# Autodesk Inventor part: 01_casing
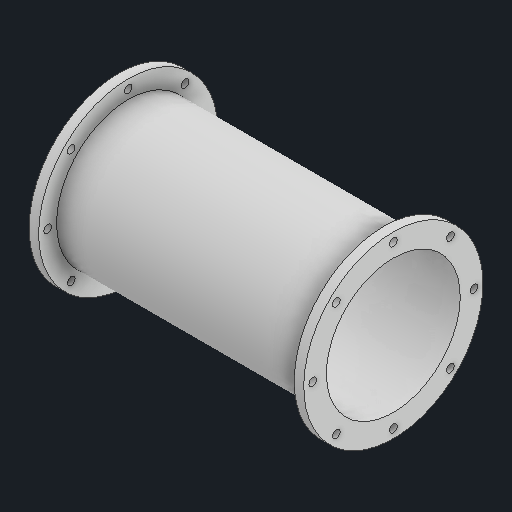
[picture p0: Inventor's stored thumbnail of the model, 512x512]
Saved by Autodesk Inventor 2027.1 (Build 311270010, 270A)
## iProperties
Created: 2026-10
Part Number: 01_casing
Material: Generic
Document SubType Name: Modeling
Designer: BHAVAN KUMAR
Density: 1 g/cm^3
Appearance: Default
Title: Turbojet Casing
Part Number: 01-CASING
Description: Outer casing tube with flanges
Author: BHAVAN KUMAR
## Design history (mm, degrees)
sketch "Sketch1"
  geometry: L1 (0, 0)-(350, 0); L2 (0, 60)-(230, 60); L3 (230, 60)-(230, 56); L4 (230, 56)-(0, 56); L5 (0, 56)-(0, 60)
  constraints: 10 end point, 2 horizontal, 2 parallel, 1 perpendicular
  dimensions: "d8" = 230 distance of L2.start L2.end (= casing_len); "d9" = 60 distance from line of L2 L1.end (= 0.5 x casing_od); "d10" = 56 distance of L1.start L4.end (= 0.5 x casing_od - casing_wall); "d11" = 0 distance from line of L1.start L5
revolve "Revolution1" sketch "Sketch1" stored, may be unused: angle "d12" = 90 deg
sketch "Sketch2"
  geometry: L1 (0, 75)-(8, 75); L2 (8, 75)-(8, 60); L3 (8, 60)-(0, 60); L4 (0, 60)-(0, 75); L5 (0, -60)-(0, 60) reference; L6 (222, 75)-(230, 75); L7 (230, 75)-(230, 60); L8 (230, 60)-(222, 60); L9 (222, 60)-(222, 75); 1 further point
  constraints: 16 end point, 4 parallel, 2 horizontal, 2 perpendicular
  dimensions: "d13" = 8 distance of L1.start L1.end (= flange_t); "d14" = 60 distance from line of point (0, 0) L3 (= 0.5 x casing_od); "d15" = 75 distance from line of point (0, 0) L1 (= 0.5 x flange_od); "d16" = 0 distance between parallel lines of L5 L4; "d17" = 222 distance between parallel lines of L5 L9 (= casing_len - flange_t); "d18" = 8 distance of L6.start L6.end (= flange_t); "d19" = 0 distance between parallel lines of L3 L8; "d20" = 0 distance between parallel lines of L6 L1
revolve "Revolution2" sketch "Sketch2" stored, may be unused: angle "d21" = 90 deg
workplane "Work Plane1"
sketch "Sketch3"
  geometry: C1 r 75 at (0, 0) reference; C2 r 56 at (0, 0) reference; C3 r 3.25 at (0, 67.5); C4 r 60 at (0, 0) reference; 1 further point
  constraints: 1 centre point
  dimensions: "d26" = 6.5 diameter of C3 (= bolt_dia); "d27" = 67.5 distance of point (0, 0) C3.centre (= 0.5 x bolt_pcd)
extrude "Extrusion1" cut sketch "Sketch3" distance "d28" = 8 (= flange_t); taper "d29" = 0 deg
pattern_circular "Circular Pattern1" dims angle "d31" = 360 deg
workplane "Work Plane2"
mirror "Mirror1"
body "Solid1"
other parameters: "casing_len" = 230 [user parameter; used in 3 equation terms], "casing_wall" = 4 [user parameter; used in 1 equation term], "flange_t" = 8 [user parameter; used in 4 equation terms], "bolt_dia" = 6.5 [user parameter; used in 1 equation term], "bolt_pcd" = 135 [user parameter; used in 1 equation term], "d25" = 0, "d33" = 115 (= 0.5 x casing_len)
